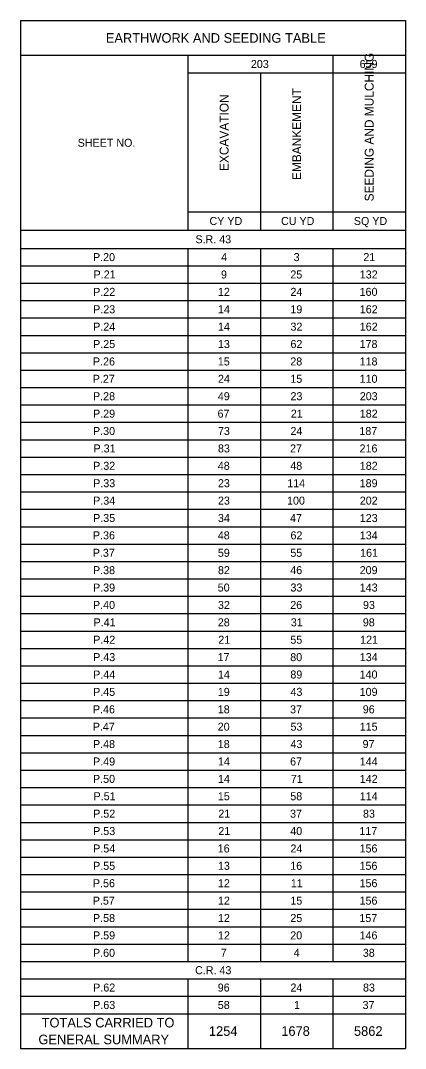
# Model space of a CAD drawing. Extents: x -9.3 to 90.7, y -9.7 to 44.8.
# Drawn here: x 83.99 to 90.72, y 26.83 to 44.81 of the extents above; entities that cross this region are included whole.
import ezdxf

# ---------------------------------------------------------------- set-up
doc = ezdxf.new("R2010")
doc.units = 0
doc.layers.add('SH_Text', color=7, linetype='Continuous')

msp = doc.modelspace()

# ---------------------------------------------------------------- linework, layer by layer
at = {"layer": 'SH_Text'}
for p, q in [((83.994, 44.814), (90.724, 44.814)), ((83.994, 44.814), (83.994, 26.827)), ((90.724, 44.814), (90.724, 26.827)), ((83.994, 44.206), (90.724, 44.206)), ((86.92, 44.206), (86.92, 41.147)), ((89.456, 44.206), (89.456, 41.147)), ((86.92, 43.901), (90.724, 43.901)), ((88.188, 43.901), (88.188, 41.147)), ((86.92, 41.467), (90.724, 41.467)), ((83.994, 41.147), (90.724, 41.147)), ((83.994, 40.827), (90.724, 40.827)), ((86.92, 40.827), (86.92, 28.349)), ((88.188, 40.827), (88.188, 28.349)), ((89.456, 40.827), (89.456, 28.349)), ((83.994, 40.523), (90.724, 40.523)), ((83.994, 40.219), (90.724, 40.219)), ((83.994, 39.914), (90.724, 39.914)), ((83.994, 39.61), (90.724, 39.61)), ((83.994, 39.306), (90.724, 39.306)), ((83.994, 39.001), (90.724, 39.001)), ((83.994, 38.697), (90.724, 38.697)), ((83.994, 38.393), (90.724, 38.393)), ((83.994, 38.088), (90.724, 38.088)), ((83.994, 37.784), (90.724, 37.784)), ((83.994, 37.48), (90.724, 37.48)), ((83.994, 37.175), (90.724, 37.175)), ((83.994, 36.871), (90.724, 36.871)), ((83.994, 36.567), (90.724, 36.567)), ((83.994, 36.262), (90.724, 36.262)), ((83.994, 35.958), (90.724, 35.958)), ((83.994, 35.654), (90.724, 35.654)), ((83.994, 35.349), (90.724, 35.349)), ((83.994, 35.045), (90.724, 35.045)), ((83.994, 34.741), (90.724, 34.741)), ((83.994, 34.436), (90.724, 34.436)), ((83.994, 34.132), (90.724, 34.132)), ((83.994, 33.827), (90.724, 33.827)), ((83.994, 33.523), (90.724, 33.523)), ((83.994, 33.219), (90.724, 33.219)), ((83.994, 32.914), (90.724, 32.914)), ((83.994, 32.61), (90.724, 32.61)), ((83.994, 32.306), (90.724, 32.306)), ((83.994, 32.001), (90.724, 32.001)), ((83.994, 31.697), (90.724, 31.697)), ((83.994, 31.393), (90.724, 31.393)), ((83.994, 31.088), (90.724, 31.088)), ((83.994, 30.784), (90.724, 30.784)), ((83.994, 30.48), (90.724, 30.48)), ((83.994, 30.175), (90.724, 30.175)), ((83.994, 29.871), (90.724, 29.871)), ((83.994, 29.567), (90.724, 29.567)), ((83.994, 29.262), (90.724, 29.262)), ((83.994, 28.958), (90.724, 28.958)), ((83.994, 28.654), (90.724, 28.654)), ((83.994, 28.349), (90.724, 28.349)), ((83.994, 28.045), (90.724, 28.045)), ((86.92, 28.045), (86.92, 27.436)), ((88.188, 28.045), (88.188, 27.436)), ((89.456, 28.045), (89.456, 27.436)), ((83.994, 27.741), (90.724, 27.741)), ((83.994, 27.436), (90.724, 27.436)), ((86.92, 27.436), (86.92, 26.827)), ((88.188, 27.436), (88.188, 26.827)), ((89.456, 27.436), (89.456, 26.827)), ((83.994, 26.827), (90.724, 26.827))]:
    msp.add_line(p, q, dxfattribs=at)

# ---------------------------------------------------------------- texts
for s, height, p in [('EARTHWORK AND SEEDING TABLE', 0.168, (85.485, 44.426)), ('203', 0.14, (88.022, 43.984)), ('659', 0.14, (89.923, 43.984)), ('SHEET NO.', 0.14, (84.993, 42.606)), ('CY YD', 0.14, (87.298, 41.237)), ('CU YD', 0.14, (88.549, 41.237)), ('SQ YD', 0.14, (89.822, 41.237)), ('S.R. 43', 0.14, (87.052, 40.917)), ('P.20', 0.14, (85.261, 40.605)), ('4', 0.14, (87.502, 40.605)), ('3', 0.14, (88.77, 40.605)), ('21', 0.14, (89.988, 40.605)), ('P.21', 0.14, (85.271, 40.301)), ('9', 0.14, (87.499, 40.301)), ('25', 0.14, (88.712, 40.301)), ('132', 0.14, (89.926, 40.301)), ('P.22', 0.14, (85.264, 39.997)), ('12', 0.14, (87.446, 39.997)), ('24', 0.14, (88.714, 39.997)), ('160', 0.14, (89.923, 39.997)), ('P.23', 0.14, (85.264, 39.692)), ('14', 0.14, (87.446, 39.692)), ('19', 0.14, (88.712, 39.692)), ('162', 0.14, (89.926, 39.692)), ('P.24', 0.14, (85.264, 39.388)), ('14', 0.14, (87.446, 39.388)), ('32', 0.14, (88.714, 39.388)), ('162', 0.14, (89.926, 39.388)), ('P.25', 0.14, (85.263, 39.084)), ('13', 0.14, (87.446, 39.084)), ('62', 0.14, (88.714, 39.084)), ('178', 0.14, (89.923, 39.084)), ('P.26', 0.14, (85.26, 38.779)), ('15', 0.14, (87.444, 38.779)), ('28', 0.14, (88.711, 38.779)), ('118', 0.14, (89.923, 38.779)), ('P.27', 0.14, (85.257, 38.475)), ('24', 0.14, (87.446, 38.475)), ('15', 0.14, (88.712, 38.475)), ('110', 0.14, (89.923, 38.475)), ('P.28', 0.14, (85.261, 38.171)), ('49', 0.14, (87.444, 38.171)), ('23', 0.14, (88.714, 38.171)), ('203', 0.14, (89.926, 38.171)), ('P.29', 0.14, (85.262, 37.866)), ('67', 0.14, (87.439, 37.866)), ('21', 0.14, (88.72, 37.866)), ('182', 0.14, (89.926, 37.866)), ('P.30', 0.14, (85.261, 37.562)), ('73', 0.14, (87.446, 37.562)), ('24', 0.14, (88.714, 37.562)), ('187', 0.14, (89.919, 37.562)), ('P.31', 0.14, (85.271, 37.257)), ('83', 0.14, (87.446, 37.257)), ('27', 0.14, (88.707, 37.257)), ('216', 0.14, (89.922, 37.257)), ('P.32', 0.14, (85.264, 36.953)), ('48', 0.14, (87.443, 36.953)), ('48', 0.14, (88.711, 36.953)), ('182', 0.14, (89.926, 36.953)), ('P.33', 0.14, (85.264, 36.649)), ('23', 0.14, (87.446, 36.649)), ('114', 0.14, (88.658, 36.649)), ('189', 0.14, (89.924, 36.649)), ('P.34', 0.14, (85.264, 36.344)), ('23', 0.14, (87.446, 36.344)), ('100', 0.14, (88.654, 36.344)), ('202', 0.14, (89.926, 36.344)), ('P.35', 0.14, (85.263, 36.04)), ('34', 0.14, (87.446, 36.04)), ('47', 0.14, (88.707, 36.04)), ('123', 0.14, (89.926, 36.04)), ('P.36', 0.14, (85.26, 35.736)), ('48', 0.14, (87.443, 35.736)), ('62', 0.14, (88.714, 35.736)), ('134', 0.14, (89.926, 35.736)), ('P.37', 0.14, (85.257, 35.431)), ('59', 0.14, (87.444, 35.431)), ('55', 0.14, (88.712, 35.431)), ('161', 0.14, (89.932, 35.431)), ('P.38', 0.14, (85.261, 35.127)), ('82', 0.14, (87.446, 35.127)), ('46', 0.14, (88.71, 35.127)), ('209', 0.14, (89.924, 35.127)), ('P.39', 0.14, (85.262, 34.823)), ('50', 0.14, (87.442, 34.823)), ('33', 0.14, (88.714, 34.823)), ('143', 0.14, (89.926, 34.823)), ('P.40', 0.14, (85.261, 34.518)), ('32', 0.14, (87.446, 34.518)), ('26', 0.14, (88.71, 34.518)), ('93', 0.14, (89.982, 34.518)), ('28', 0.14, (87.443, 34.214)), ('31', 0.14, (88.72, 34.214)), ('98', 0.14, (89.979, 34.214)), ('P.41', 0.14, (85.271, 34.214)), ('P.42', 0.14, (85.264, 33.91)), ('21', 0.14, (87.452, 33.91)), ('55', 0.14, (88.712, 33.91)), ('121', 0.14, (89.932, 33.91)), ('P.43', 0.14, (85.264, 33.605)), ('17', 0.14, (87.439, 33.605)), ('80', 0.14, (88.71, 33.605)), ('134', 0.14, (89.926, 33.605)), ('P.44', 0.14, (85.264, 33.301)), ('14', 0.14, (87.446, 33.301)), ('89', 0.14, (88.712, 33.301)), ('140', 0.14, (89.923, 33.301)), ('P.45', 0.14, (85.263, 32.997)), ('19', 0.14, (87.444, 32.997)), ('43', 0.14, (88.714, 32.997)), ('109', 0.14, (89.924, 32.997)), ('P.46', 0.14, (85.26, 32.692)), ('18', 0.14, (87.443, 32.692)), ('37', 0.14, (88.707, 32.692)), ('96', 0.14, (89.978, 32.692)), ('P.47', 0.14, (85.257, 32.388)), ('20', 0.14, (87.442, 32.388)), ('53', 0.14, (88.714, 32.388)), ('115', 0.14, (89.925, 32.388)), ('P.48', 0.14, (85.261, 32.084)), ('18', 0.14, (87.443, 32.084)), ('43', 0.14, (88.714, 32.084)), ('97', 0.14, (89.975, 32.084)), ('P.49', 0.14, (85.262, 31.779)), ('14', 0.14, (87.446, 31.779)), ('67', 0.14, (88.707, 31.779)), ('144', 0.14, (89.926, 31.779)), ('P.50', 0.14, (85.261, 31.475)), ('14', 0.14, (87.446, 31.475)), ('71', 0.14, (88.72, 31.475)), ('142', 0.14, (89.926, 31.475)), ('P.51', 0.14, (85.271, 31.171)), ('15', 0.14, (87.444, 31.171)), ('58', 0.14, (88.711, 31.171)), ('114', 0.14, (89.926, 31.171)), ('P.52', 0.14, (85.264, 30.866)), ('21', 0.14, (87.452, 30.866)), ('37', 0.14, (88.707, 30.866)), ('83', 0.14, (89.982, 30.866)), ('P.53', 0.14, (85.264, 30.562)), ('21', 0.14, (87.452, 30.562)), ('40', 0.14, (88.71, 30.562)), ('117', 0.14, (89.919, 30.562)), ('16', 0.14, (87.442, 30.257)), ('24', 0.14, (88.714, 30.257)), ('156', 0.14, (89.922, 30.257)), ('P.54', 0.14, (85.264, 30.257)), ('P.55', 0.14, (85.263, 29.953)), ('13', 0.14, (87.446, 29.953)), ('16', 0.14, (88.71, 29.953)), ('156', 0.14, (89.922, 29.953)), ('P.56', 0.14, (85.26, 29.649)), ('12', 0.14, (87.446, 29.649)), ('11', 0.14, (88.72, 29.649)), ('156', 0.14, (89.922, 29.649)), ('P.57', 0.14, (85.257, 29.344)), ('12', 0.14, (87.446, 29.344)), ('15', 0.14, (88.712, 29.344)), ('156', 0.14, (89.922, 29.344)), ('P.58', 0.14, (85.261, 29.04)), ('12', 0.14, (87.446, 29.04)), ('25', 0.14, (88.712, 29.04)), ('157', 0.14, (89.919, 29.04)), ('P.59', 0.14, (85.262, 28.736)), ('12', 0.14, (87.446, 28.736)), ('20', 0.14, (88.71, 28.736)), ('146', 0.14, (89.922, 28.736)), ('P.60', 0.14, (85.261, 28.431)), ('7', 0.14, (87.495, 28.431)), ('4', 0.14, (88.77, 28.431)), ('38', 0.14, (89.979, 28.431)), ('C.R. 43', 0.14, (87.046, 28.127)), ('P.62', 0.14, (85.264, 27.823)), ('96', 0.14, (87.442, 27.823)), ('24', 0.14, (88.714, 27.823)), ('83', 0.14, (89.982, 27.823)), ('P.63', 0.14, (85.264, 27.518)), ('58', 0.14, (87.443, 27.518)), ('1', 0.14, (88.776, 27.518)), ('37', 0.14, (89.975, 27.518)), ('TOTALS CARRIED TO ', 0.168, (84.363, 27.195)), ('1254', 0.168, (87.288, 27.048)), ('1678', 0.168, (88.553, 27.048)), ('5862', 0.168, (89.824, 27.048)), ('GENERAL SUMMARY', 0.168, (84.307, 26.901))]:
    msp.add_text(s, height=height, dxfattribs=at).set_placement(p)
for s, height, p in [('SEEDING AND MULCHING', 0.15556, (90.168, 41.65)), ('EMBANKEMENT', 0.15556, (88.9, 42.024)), ('EXCAVATION', 0.1556, (87.631, 42.182))]:
    msp.add_text(s, height=height, rotation=90, dxfattribs=at).set_placement(p)

doc.saveas('drawing.dxf')
